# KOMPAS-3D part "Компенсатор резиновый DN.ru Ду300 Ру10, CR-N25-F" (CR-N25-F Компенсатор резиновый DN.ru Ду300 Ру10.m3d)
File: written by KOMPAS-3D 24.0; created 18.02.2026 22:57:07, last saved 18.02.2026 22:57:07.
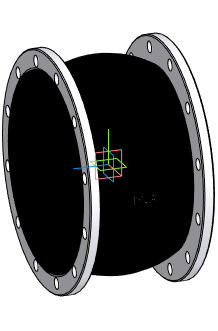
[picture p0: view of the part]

Document properties: Автор: DN.RU; Полное имя файла: D:\PROJECT CAD\DN.RU\...178(1)(ACTUALE). CR-N25-F Компенсатор резиновый DN.ru Ру10-16\DN300_PN10\CR-N25-F Компенсатор резиновый DN.ru Ду300 Ру10.m3d

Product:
- Body: Твердое тело2  | qty 1
    Масса: 94.24882
- Part/product: Компенсатор резиновый DN.ru Ду300 Ру10  | designation CR-N25-F
    Масса: 30
    Раздел спецификации: Прочие изделия
    Комментарий: D140-02399
    Примечание: D140-02399
    additional columns: Типовые

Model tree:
1. Твердое тело2  (labels: Твердое тело2)

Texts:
  CR-N25-F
